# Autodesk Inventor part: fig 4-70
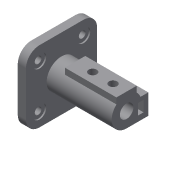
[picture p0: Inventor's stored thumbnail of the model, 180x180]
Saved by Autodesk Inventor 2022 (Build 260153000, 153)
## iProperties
Created: 2001-12
Part Number: fig 4-70
Document SubType Name: Modeling
Designer: Renu Muthoo
Density: 1 g/cm^3
Material: Generic
Appearance: Default
Control State: 0
Master: False
Checked Out: False
Shininess: 77.0
Length Units: 11269
Angle Units: 11279
Time Units: 11290
Mass Units: 11283
Length Display Precision: 3
Angle Display Precision: 2
Density: 0.0
Volumn: 0.0
Area: 0.0
PropertySet Name: Model Information
Author: Renu Muthoo
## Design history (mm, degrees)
node "Sketch1"
sketch "Sketch2"
  geometry: L1 (24.44, 30.488)-(-40.56, 30.488); L2 (-60.56, 10.488)-(-60.56, -54.512); L3 (-40.56, -74.512)-(24.44, -74.512); L4 (44.44, -54.512)-(44.44, 10.488); A1 r 20 centre (24.44, 10.488) between (44.44, 10.488) and (24.44, 30.488); A2 r 20 centre (-40.56, 10.488) between (-40.56, 30.488) and (-60.56, 10.488); A3 r 20 centre (-40.56, -54.512) between (-60.56, -54.512) and (-40.56, -74.512); A4 r 20 centre (24.44, -54.512) between (24.44, -74.512) and (44.44, -54.512); 2 further points
  constraints: 8 end point, 8 point on circle, 8 tangent, 4 centre point, 4 point on line, 3 equal radius, 2 parallel, 2 perpendicular, 1 horizontal
  dimensions: "d1" = 20 radius of A1; "d2" = 105 distance between parallel lines of L2 L4
extrude "Extrusion1" new body sketch "Sketch2" distance "d3" = 12; taper "d4" = 0 deg
sketch "Sketch3"
  geometry: A1 r 20 centre (-24.44, 10.488) between (-24.44, 30.488) and (-44.44, 10.488) reference; A2 r 20 centre (-24.44, -54.512) between (-44.44, -54.512) and (-24.44, -74.512) reference; A3 r 20 centre (40.56, -54.512) between (40.56, -74.512) and (60.56, -54.512) reference; A4 r 20 centre (40.56, 10.488) between (60.56, 10.488) and (40.56, 30.488) reference
hole "Hole1" sketch "Sketch3" at (-24.44, 10.488), (-24.44, -54.512), (40.56, 10.488), (40.56, -54.512) diameter "d5" = 10; stored, may be unused: countersink angle "d9" = 82 deg, drill point angle "d11" = 118 deg; dims "d6" = 6, "d7" = 20, "d8" = 2, "d10" = 8
sketch "Sketch4"
  geometry: L1 (-24.44, 30.488)-(40.56, 30.488) reference; L2 (-44.44, -54.512)-(-44.44, 10.488) reference; C1 r 22 at (8.06, -22.012)
  constraints: 1 centre point
  dimensions: "d12" = 52.5 distance from line of L2 C1.centre; "d13" = 52.5 distance from line of L1 C1.centre; "d14" = 44 diameter of C1
extrude "Extrusion2" join sketch "Sketch4" distance "d15" = 96; taper "d16" = 0 deg
sketch "Sketch5"
  geometry: L1 (-15, 16.093)-(15, 16.093); L2 (15, 16.093)-(15, 25); L3 (15, 25)-(-15, 25); L4 (-15, 25)-(-15, 16.093); 1 further point
  constraints: 8 end point, 2 parallel, 1 horizontal, 1 perpendicular, 2 other
  dimensions: "d17" = 30 distance of L2.end L3.end; "d18" = 25 distance from line of point (0, 0) L3; "d19" = 15 distance from line of point (0, 0) L4
extrude "Extrusion3" join sketch "Sketch5" distance "d20" = 76; taper "d21" = 0 deg
sketch "Sketch6"
  geometry: L1 (8, -44.012)-(40.06, -44.012); L2 (40.06, -44.012)-(40.06, -14.012); L3 (40.06, -14.012)-(8, -14.012); L4 (8, -14.012)-(8, -44.012); A1 r 22 centre (8.06, -22.012) between (-6.94, -5.918) and (23.06, -5.918) reference
  constraints: 8 end point, 2 parallel, 1 horizontal, 1 perpendicular, 1 tangent
  dimensions: "d22" = 32 distance from line of A1.centre L2; "d23" = 30 distance of L1.end L2.end
extrude "Extrusion4" join sketch "Sketch6" distance "d24" = 57; taper "d25" = 0 deg
sketch "Sketch7"
  geometry: L1 (25.06, -20.012)-(33.06, -20.012); L2 (33.06, -20.012)-(33.06, -36.012); L3 (33.06, -36.012)-(25.06, -36.012); L4 (25.06, -36.012)-(25.06, -20.012); A1 r 22 centre (8.06, -22.012) between (-6.94, -5.918) and (8, -44.012) reference
  constraints: 8 end point, 2 parallel, 1 horizontal, 1 perpendicular
  dimensions: "d26" = 8 distance of L2.end L3.end; "d27" = 16 distance of L1.end L2.end; "d28" = 25 distance from line of A1.centre L2; "d29" = 2 vertical distance of A1.centre L1.start
extrude "Extrusion5" cut sketch "Sketch7" distance "d30" = 35; taper "d31" = 0 deg
sketch "Sketch8"
  geometry: A1 r 22 centre (8.06, -22.012) between (-6.94, -5.918) and (8, -44.012) reference
hole "Hole2" sketch "Sketch8" at (8.06, -22.012) diameter "d32" = 20; stored, may be unused: countersink angle "d36" = 82 deg, drill point angle "d38" = 0 deg; dims "d33" = 6, "d34" = 20, "d35" = 2, "d37" = 96
sketch "Sketch9"
  geometry: L1 (0, 0)-(0, 76) reference; L2 (30, 0)-(0, 0) reference; 2 further points
  dimensions: "d39" = 20 distance from line of L2 point (15, 20); "d40" = 15 distance from line of L1 point (15, 20); "d41" = 30 distance of point (15, 50) point (15, 20)
hole "Hole3" sketch "Sketch9" at (15, 20), (15, 50) diameter "d42" = 12; stored, may be unused: countersink angle "d46" = 82 deg, drill point angle "d48" = 0 deg; dims "d43" = 6, "d44" = 20, "d45" = 2, "d47" = 25
sketch "Sketch10"
  geometry: L1 (30, 0)-(0, 0) reference; L2 (30, 0)-(30, 57) reference; 2 further points
  dimensions: "d49" = 15 distance from line of L1 point (15, 15); "d50" = 15 distance from line of L2 point (15, 15); "d51" = 22 distance of point (15, 37) point (15, 15)
hole "Hole4" sketch "Sketch10" at (15, 15), (15, 37) diameter "d52" = 10; stored, may be unused: countersink angle "d56" = 82 deg, drill point angle "d58" = 0 deg; dims "d53" = 6, "d54" = 20, "d55" = 2, "d57" = 7
body "Solid1"
